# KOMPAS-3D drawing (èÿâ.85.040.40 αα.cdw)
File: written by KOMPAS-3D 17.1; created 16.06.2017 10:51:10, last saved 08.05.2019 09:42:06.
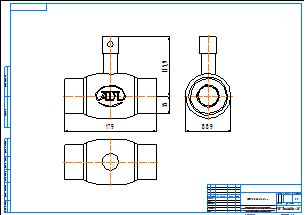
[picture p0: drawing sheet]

Sheet 1: A2, landscape

Title block, sheet 1: name: КШГ.85.040.40 рр; material: Внимание! Данный продукт является объектом авторского права ООО «Торговый Дом АДЛ». / Запрещается изменение, копирование, распространение / (в том числе путем копирования на другие сайты и ресурсы в Интернете) / или любое иное использование информации и объектов без предварительного / согласия правообладателя (ООО «Торговый Дом АДЛ»).; scale: 1:1; sheets: 1; organisation: ООО "Торговый дом АДЛ"; sheet format: A2; stored path: C:\Users\tra\Desktop\2д чертежи\Шаровые краны БИВАЛ\КШ_Бивал_серия_82_85\KOMPAS 2D\КШГ.85.040.40 рр.cdw

Views: Спереди 1, Проекционный вид 2, Проекционный вид 3
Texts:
  Klimkovich
  ADL
Dimensions and other numbers on the sheet: 179; 115,9; 35; 88,9; 1:1; 1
